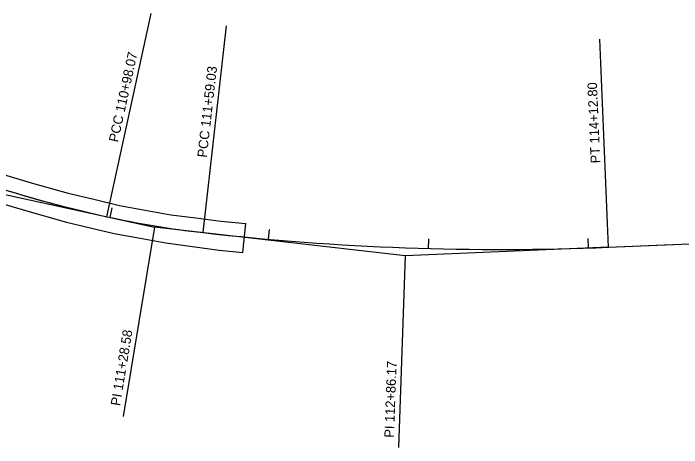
# Model space of a CAD drawing. Extents: x 834421 to 837111, y 495679 to 497078.
# Drawn here: x 835791.5 to 836209, y 496701.7 to 496973 of the extents above; entities that cross this region are included whole.
import ezdxf

# ---------------------------------------------------------------- set-up
doc = ezdxf.new("R2010")
doc.units = 0
for name, color, linetype in [('EXISTING CENTERLINE', 7, 'Continuous'), ('R_Horz Alg', 7, 'Continuous'), ('R_Horz Alg Annot', 7, 'Continuous'), ('R_Horz Alg Stationing', 7, 'Continuous'), ('R_Proposed Road', 7, 'Continuous'), ('Transportation__x002e__STATEWIDE_HIGHWAY_LOGMILES_AHTD_point', 7, 'Continuous')]:
    doc.layers.add(name, color=color, linetype=linetype)

msp = doc.modelspace()

# ---------------------------------------------------------------- linework, layer by layer
at = {"layer": 'EXISTING CENTERLINE'}
msp.add_line((836163.35, 496826.92), (836203.31, 496828.58), dxfattribs=at)
for centre, radius, start, end in [((836012.53, 497592.42), 763.94, 244.97523, 257.70667), ((835978.28, 497435.28), 603.11, 257.70667, 263.49693), ((836095.38, 498462.53), 1637.02, 263.49693, 272.37944), ((836181.65, 496386.56), 440.74, 92.379325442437, 92.37933007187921)]:
    msp.add_arc(centre, radius, start, end, dxfattribs=at)
at = {"layer": 'R_Horz Alg'}
msp.add_line((836163.33, 496826.92), (836250.46, 496830.54), dxfattribs=at)
msp.add_line((836163.33, 496826.92), (836250.46, 496830.54), dxfattribs=at)
for centre, radius, start, end in [((836012.53, 497592.42), 763.94, 246.8875, 257.70667), ((836012.53, 497592.42), 763.94, 246.8875, 257.70667), ((835978.28, 497435.28), 603.11, 257.70667, 263.49722), ((835978.28, 497435.28), 603.11, 257.70667, 263.49722), ((836095.38, 498462.53), 1637.02, 263.49722, 272.37917), ((836095.38, 498462.53), 1637.02, 263.49722, 272.37917)]:
    msp.add_arc(centre, radius, start, end, dxfattribs=at)
at = {"layer": 'R_Horz Alg Annot'}
for p, q in [((835779.19, 496861.39), (835879.68, 496839.5)), ((836036.3, 496821.64), (835879.68, 496839.5)), ((836163.33, 496826.92), (836249.7, 496830.51)), ((836163.33, 496826.92), (836036.3, 496821.64))]:
    msp.add_line(p, q, dxfattribs=at)
for points in [[(835849.87, 496845.99), (835877.55, 496973.01)], [(835909.98, 496836.04), (835924.7, 496965.21)], [(836163.33, 496826.92), (836157.94, 496956.81)], [(835879.68, 496839.5), (835860.08, 496721.11)], [(836036.3, 496821.64), (836031.99, 496701.72)]]:
    msp.add_lwpolyline(points, dxfattribs=at)
for centre, radius, start, end in [((835978.28, 497435.28), 603.11, 257.70667, 263.49722), ((836095.38, 498462.53), 1637.02, 263.49722, 272.37917)]:
    msp.add_arc(centre, radius, start, end, dxfattribs=at)
at = {"layer": 'R_Horz Alg Stationing'}
for points in [[(835853.01, 496851.45), (835851.75, 496845.58)], [(835951.27, 496837.89), (835950.74, 496831.91)], [(836050.72, 496832.12), (836050.56, 496826.12)], [(836150.34, 496832.44), (836150.54, 496826.44)]]:
    msp.add_lwpolyline(points, dxfattribs=at)
at = {"layer": 'R_Proposed Road'}
for p, q in [((835791.48, 496870.48), (835791.49, 496870.53)), ((835934.87, 496823.71), (835936.63, 496841.72))]:
    msp.add_line(p, q, dxfattribs=at)
for points in [[(835791.48, 496870.48), (835804.14, 496866.7), (835825.64, 496860.66), (835841.66, 496856.85), (835857.68, 496853.04), (835873.71, 496850.12), (835889.74, 496847.2), (835905.42, 496845.19), (835921.09, 496843.17), (835936.63, 496841.72)], [(835786.34, 496853.69), (835800.56, 496849.36), (835824.59, 496842.64), (835839.54, 496839.06), (835854.5, 496835.48), (835870.61, 496832.58), (835886.72, 496829.69), (835903.42, 496827.39), (835920.11, 496825.1), (835934.87, 496823.71)]]:
    msp.add_lwpolyline(points, dxfattribs=at)
msp.add_arc((835940.09, 497393.88), 544.04, 243.1853, 254.149, dxfattribs=at)
at = {"layer": 'Transportation__x002e__STATEWIDE_HIGHWAY_LOGMILES_AHTD_point'}
for p, q in [((835794.35, 496857.4), (835794.35, 496857.4)), ((835893.75, 496837.4), (835893.75, 496837.4)), ((835994.93, 496829.89), (835994.93, 496829.89)), ((836197.87, 496830.08), (836197.87, 496830.08)), ((836096.38, 496827.84), (836096.38, 496827.84))]:
    msp.add_line(p, q, dxfattribs=at)

# ---------------------------------------------------------------- texts
at = {"layer": 'R_Horz Alg Annot'}
for s, rotation, p in [('PCC 110+98.07', 77.7067, (835856.86, 496892.16)), ('PCC 111+59.03', 83.4972, (835912.28, 496882.71)), ('PT 114+12.80', 92.3792, (836158.15, 496879.46)), ('PI 111+28.58', 80.6019, (835858.1, 496727.52)), ('PI 112+86.17', 87.9382, (836029.2, 496707.83))]:
    msp.add_text(s, height=6, rotation=rotation, dxfattribs=at).set_placement(p)

doc.saveas('drawing.dxf')
